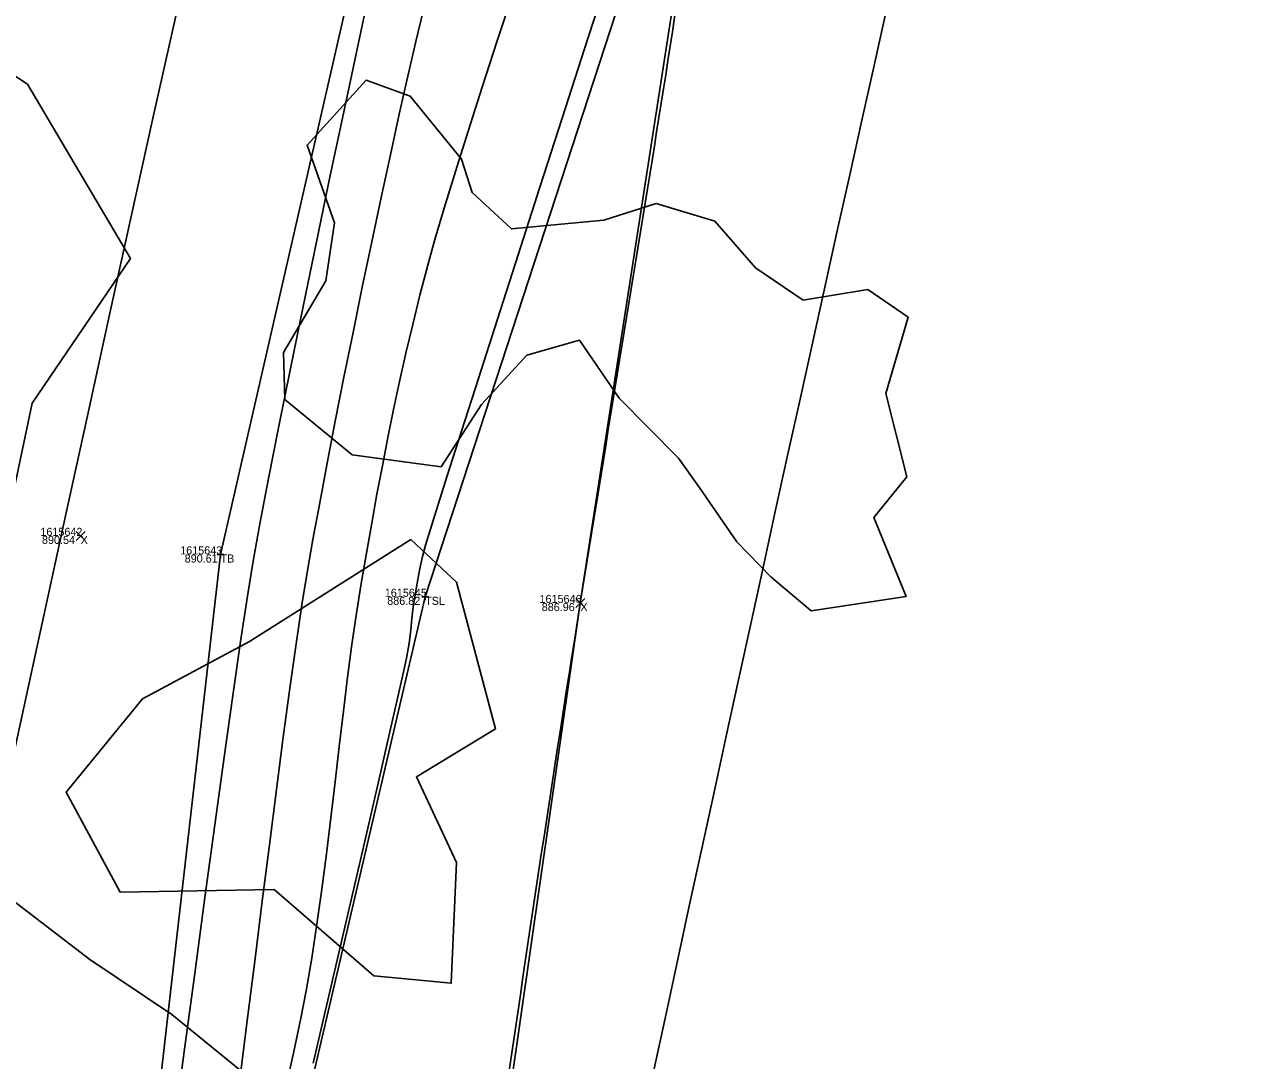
# Model space of a CAD drawing. Extents: x 1957117 to 1971063, y 701601 to 715861.
# Drawn here: x 1962867.2 to 1962920.6, y 704121 to 704165.9 of the extents above; entities that cross this region are included whole.
import ezdxf

# ---------------------------------------------------------------- set-up
doc = ezdxf.new("R2010")
doc.units = 0
for name, color, linetype in [('AP_X_Lights', 7, 'Continuous'), ('DT_X_Break_Line', 7, 'Continuous'), ('DT_X_Contour_Major', 7, 'Continuous'), ('DT_X_Contour_Minor', 7, 'Continuous'), ('DT_X_TIN_Hull', 7, 'Continuous'), ('GE_X_CL_20', 7, 'Continuous'), ('HY_X_Water_Edge', 7, 'Continuous'), ('PV_P_Drive', 7, 'Continuous'), ('PV_P_Shoulder', 7, 'Continuous'), ('RS_Raster1', 7, 'Continuous'), ('RW_X_Esmt_RR', 7, 'Continuous'), ('SC_Scratch1', 7, 'Continuous'), ('VG_X_Tree_Line_Rt', 7, 'Continuous')]:
    doc.layers.add(name, color=color, linetype=linetype)

msp = doc.modelspace()

# ---------------------------------------------------------------- linework, layer by layer
at = {"layer": 'AP_X_Lights'}
for p, q in [((1962869.397, 704143.569), (1962869.785, 704143.959)), ((1962869.397, 704143.959), (1962869.785, 704143.569)), ((1962891.047, 704140.659), (1962891.435, 704141.049)), ((1962891.047, 704141.049), (1962891.435, 704140.659))]:
    msp.add_line(p, q, dxfattribs=at)
at = {"layer": 'DT_X_Break_Line'}
for points in [[(1962943.949, 704328.022), (1962905.467, 704230.979), (1962897.382, 704180.529), (1962884.517, 704141.123), (1962873.17, 704092.531), (1962861.357, 704043.493), (1962859.494, 703994.644), (1962847.336, 703945.791), (1962836.6, 703895.416), (1962825.781, 703849.035), (1962810.838, 703749.706), (1962817.97, 703697.316), (1962817.962, 703593.874), (1962775.136, 703505.909), (1962781.746, 703450.546)], [(1962773.34, 703451.658), (1962770.93, 703504.314), (1962788.88, 703601.143), (1962786.588, 703649.417), (1962805.729, 703698.412), (1962807.65, 703752.461), (1962811.117, 703798.827), (1962819.396, 703847.658), (1962831.04, 703896.555), (1962840.848, 703945.281), (1962846.53, 703997.82), (1962856.691, 704040.715), (1962869.943, 704092.882), (1962875.651, 704142.958), (1962884.844, 704183.087), (1962898.502, 704228.866), (1962909.862, 704285.214)]]:
    msp.add_lwpolyline(points, dxfattribs=at)
at = {"layer": 'DT_X_Contour_Major'}
msp.add_lwpolyline([(1962882.214, 704167.881), (1962881.625, 704165.127), (1962881.019, 704162.276), (1962880.409, 704159.384), (1962879.807, 704156.506), (1962879.226, 704153.698), (1962878.678, 704151.016), (1962878.175, 704148.516), (1962877.731, 704146.254), (1962877.357, 704144.285), (1962877.066, 704142.665), (1962876.819, 704141.148), (1962876.523, 704139.187), (1962876.183, 704136.842), (1962875.807, 704134.173), (1962875.402, 704131.237), (1962874.975, 704128.094), (1962874.533, 704124.803), (1962874.084, 704121.422), (1962873.634, 704118.012)], dxfattribs=at)
msp.add_lwpolyline([(1962882.214, 704167.881), (1962881.625, 704165.127), (1962881.019, 704162.276), (1962880.409, 704159.384), (1962879.807, 704156.506), (1962879.226, 704153.698), (1962878.678, 704151.016), (1962878.175, 704148.516), (1962877.731, 704146.254), (1962877.357, 704144.285), (1962877.066, 704142.665), (1962876.819, 704141.148), (1962876.523, 704139.187), (1962876.183, 704136.842), (1962875.807, 704134.173), (1962875.402, 704131.237), (1962874.975, 704128.094), (1962874.533, 704124.803), (1962874.084, 704121.422), (1962873.634, 704118.012)], dxfattribs=at)
at = {"layer": 'DT_X_Contour_Minor'}
for points in [[(1962892.371, 704167.814), (1962891.424, 704164.875), (1962890.457, 704161.87), (1962889.492, 704158.869), (1962888.55, 704155.942), (1962887.656, 704153.158), (1962886.831, 704150.588), (1962886.097, 704148.3), (1962885.479, 704146.364), (1962884.997, 704144.85), (1962884.675, 704143.828), (1962884.534, 704143.367), (1962884.408, 704142.873), (1962884.316, 704142.478), (1962884.242, 704142.115), (1962884.171, 704141.716), (1962884.084, 704141.213), (1962884.003, 704140.673), (1962883.946, 704140.176), (1962883.891, 704139.674), (1962883.82, 704139.117), (1962883.712, 704138.457), (1962883.598, 704137.931), (1962883.339, 704136.783), (1962882.951, 704135.087), (1962882.451, 704132.914), (1962881.856, 704130.337), (1962881.183, 704127.43), (1962880.45, 704124.264), (1962879.673, 704120.913)], [(1962892.371, 704167.814), (1962891.424, 704164.875), (1962890.457, 704161.87), (1962889.492, 704158.869), (1962888.55, 704155.942), (1962887.656, 704153.158), (1962886.831, 704150.588), (1962886.097, 704148.3), (1962885.479, 704146.364), (1962884.997, 704144.85), (1962884.675, 704143.828), (1962884.534, 704143.367), (1962884.408, 704142.873), (1962884.316, 704142.478), (1962884.242, 704142.115), (1962884.171, 704141.716), (1962884.084, 704141.213), (1962884.003, 704140.673), (1962883.946, 704140.176), (1962883.891, 704139.674), (1962883.82, 704139.117), (1962883.712, 704138.457), (1962883.598, 704137.931), (1962883.339, 704136.783), (1962882.951, 704135.087), (1962882.451, 704132.914), (1962881.856, 704130.337), (1962881.183, 704127.43), (1962880.45, 704124.264), (1962879.673, 704120.913)], [(1962888.319, 704167.279), (1962887.644, 704165.214), (1962886.995, 704163.211), (1962886.385, 704161.31), (1962885.829, 704159.549), (1962885.342, 704157.967), (1962884.937, 704156.603), (1962884.629, 704155.495), (1962884.293, 704154.195), (1962883.98, 704152.928), (1962883.687, 704151.684), (1962883.412, 704150.458), (1962883.152, 704149.24), (1962882.903, 704148.024), (1962882.664, 704146.802), (1962882.431, 704145.565), (1962882.202, 704144.307), (1962881.974, 704143.02), (1962881.745, 704141.697), (1962881.539, 704140.419), (1962881.344, 704139.061), (1962881.157, 704137.637), (1962880.974, 704136.159), (1962880.794, 704134.641), (1962880.613, 704133.097), (1962880.429, 704131.541), (1962880.238, 704129.986), (1962880.039, 704128.445), (1962879.828, 704126.933), (1962879.602, 704125.463), (1962879.359, 704124.048), (1962879.129, 704122.866), (1962878.824, 704121.415), (1962878.455, 704119.73)], [(1962888.319, 704167.279), (1962887.644, 704165.214), (1962886.995, 704163.211), (1962886.385, 704161.31), (1962885.829, 704159.549), (1962885.342, 704157.967), (1962884.937, 704156.603), (1962884.629, 704155.495), (1962884.293, 704154.195), (1962883.98, 704152.928), (1962883.687, 704151.684), (1962883.412, 704150.458), (1962883.152, 704149.24), (1962882.903, 704148.024), (1962882.664, 704146.802), (1962882.431, 704145.565), (1962882.202, 704144.307), (1962881.974, 704143.02), (1962881.745, 704141.697), (1962881.539, 704140.419), (1962881.344, 704139.061), (1962881.157, 704137.637), (1962880.974, 704136.159), (1962880.794, 704134.641), (1962880.613, 704133.097), (1962880.429, 704131.541), (1962880.238, 704129.986), (1962880.039, 704128.445), (1962879.828, 704126.933), (1962879.602, 704125.463), (1962879.359, 704124.048), (1962879.129, 704122.866), (1962878.824, 704121.415), (1962878.455, 704119.73)], [(1962884.439, 704166.506), (1962884.119, 704165.185), (1962883.771, 704163.689), (1962883.399, 704162.044), (1962883.01, 704160.279), (1962882.609, 704158.423), (1962882.202, 704156.502), (1962881.794, 704154.545), (1962881.392, 704152.58), (1962881, 704150.635), (1962880.626, 704148.737), (1962880.273, 704146.915), (1962879.948, 704145.196), (1962879.657, 704143.609), (1962879.406, 704142.181), (1962879.177, 704140.772), (1962878.927, 704139.084), (1962878.658, 704137.159), (1962878.373, 704135.039), (1962878.076, 704132.765), (1962877.771, 704130.38), (1962877.46, 704127.926), (1962877.148, 704125.445), (1962876.838, 704122.978), (1962876.533, 704120.567)], [(1962884.439, 704166.506), (1962884.119, 704165.185), (1962883.771, 704163.689), (1962883.399, 704162.044), (1962883.01, 704160.279), (1962882.609, 704158.423), (1962882.202, 704156.502), (1962881.794, 704154.545), (1962881.392, 704152.58), (1962881, 704150.635), (1962880.626, 704148.737), (1962880.273, 704146.915), (1962879.948, 704145.196), (1962879.657, 704143.609), (1962879.406, 704142.181), (1962879.177, 704140.772), (1962878.927, 704139.084), (1962878.658, 704137.159), (1962878.373, 704135.039), (1962878.076, 704132.765), (1962877.771, 704130.38), (1962877.46, 704127.926), (1962877.148, 704125.445), (1962876.838, 704122.978), (1962876.533, 704120.567)]]:
    msp.add_lwpolyline(points, dxfattribs=at)
at = {"layer": 'DT_X_TIN_Hull'}
msp.add_lwpolyline([(1962804.686, 703399.836), (1962817.962, 703593.874), (1962817.97, 703697.316), (1962826.397, 703745.681), (1962828.582, 703804.235), (1962836.461, 703844.734), (1962850.687, 703896.004), (1962867.251, 703938.846), (1962873.848, 703992.355), (1962884.135, 704091.371), (1962891.241, 704140.854), (1962897.382, 704180.529), (1962905.467, 704230.979), (1962909.862, 704285.214)], dxfattribs=at)
at = {"layer": 'GE_X_CL_20'}
msp.add_arc((1968466.781, 702923.066), 5729.578, 166.495347, 177.813939, dxfattribs=at)
at = {"layer": 'HY_X_Water_Edge'}
msp.add_spline([(1963191.723, 701994.048), (1963062.047, 702441.167), (1962863.491, 703169.356), (1962827.53, 703438.691), (1962823.213, 703537.412), (1962817.962, 703593.874), (1962817.97, 703697.316), (1962828.582, 703804.235), (1962836.461, 703844.734), (1962850.687, 703896.004), (1962867.251, 703938.846), (1962873.848, 703992.355), (1962884.135, 704091.371), (1962891.241, 704140.854), (1962897.382, 704180.529), (1962905.467, 704230.979), (1962943.949, 704328.022), (1962948.537, 704378.842), (1962964.114, 704426.264), (1963004.885, 704570.73), (1963042.054, 704716.522), (1963062.038, 704814.417), (1963072.171, 704860.237), (1963090.023, 704956.798), (1963107.066, 705031.783), (1963133.773, 705105.742), (1963148.685, 705206.74), (1963175.48, 705301.059), (1963191.635, 705353.417), (1963210.988, 705447.286), (1963219.532, 705497.27), (1963230.124, 705549.475), (1963251.052, 705591.159), (1963275.289, 705693.429), (1963292.982, 705784.032), (1963302.841, 705839.645), (1963335.126, 705936.766), (1963359.752, 706046.75), (1963389.133, 706177.299), (1963417.827, 706273.456), (1963475.868, 706451.902), (1963533.782, 706640.53), (1963553.86, 706696.984), (1963580.184, 706715.425), (1963609.172, 706718.73), (1963617.062, 706714.691), (1963619.447, 706694.678), (1963564.282, 706533.07), (1963531.853, 706395.229), (1963434.4, 706006.96), (1963354.09, 705679.186), (1963237.513, 705206.07), (1963167.369, 704892.962), (1963059.145, 704434.176), (1962907.914, 703908.742), (1962877.458, 703703.326), (1962898.357, 703412.121), (1962942.65, 703052.267), (1963048.963, 702674.866), (1963191.468, 702189.666), (1963245.396, 702019.832)], degree=3, dxfattribs=at)
at = {"layer": 'PV_P_Drive'}
for p, q in [((1962875.505, 704142.958), (1962875.797, 704142.958)), ((1962875.651, 704143.104), (1962875.651, 704142.812)), ((1962875.651, 704142.958), (1962875.651, 704142.958)), ((1962884.517, 704141.269), (1962884.517, 704140.977)), ((1962884.371, 704141.123), (1962884.663, 704141.123)), ((1962884.517, 704141.123), (1962884.517, 704141.123))]:
    msp.add_line(p, q, dxfattribs=at)
at = {"layer": 'RW_X_Esmt_RR'}
msp.add_arc((1968466.781, 702923.066), 5699.578, 166.495347, 172.904425, dxfattribs=at)
at = {"layer": 'VG_X_Tree_Line_Rt'}
for points in [[(1962882.795, 704034.298), (1962885.248, 704041.793), (1962884.482, 704055.8), (1962885.404, 704065.908), (1962882.366, 704072.7), (1962882.543, 704081.484), (1962882.619, 704089.681), (1962882.279, 704098.622), (1962881.961, 704108.953), (1962879.902, 704115.666), (1962876.89, 704120.283), (1962873.54, 704123.024), (1962869.986, 704125.403), (1962863.467, 704130.399), (1962863.467, 704130.399), (1962867.485, 704149.521), (1962871.749, 704155.787), (1962867.283, 704163.333), (1962860.619, 704167.72)], [(1962881.357, 704147.282), (1962885.212, 704146.76), (1962886.961, 704149.461), (1962888.92, 704151.595), (1962891.2, 704152.249), (1962892.92, 704149.726), (1962895.496, 704147.124), (1962896.391, 704145.881), (1962898.029, 704143.505), (1962899.498, 704141.994), (1962901.241, 704140.515), (1962905.354, 704141.132), (1962903.955, 704144.564), (1962905.391, 704146.324), (1962904.471, 704149.935), (1962905.446, 704153.24), (1962903.7, 704154.437), (1962900.896, 704153.975), (1962898.832, 704155.374), (1962897.065, 704157.397), (1962894.532, 704158.172), (1962892.254, 704157.44), (1962888.261, 704157.077), (1962886.56, 704158.638), (1962886.1, 704160.089), (1962883.871, 704162.813), (1962881.964, 704163.519), (1962879.402, 704160.698), (1962880.586, 704157.332), (1962880.212, 704154.822), (1962878.377, 704151.716), (1962878.442, 704149.668), (1962881.357, 704147.282)], [(1962876.901, 704139.185), (1962872.266, 704136.703), (1962868.962, 704132.649), (1962871.301, 704128.328), (1962877.979, 704128.433), (1962882.296, 704124.691), (1962885.648, 704124.373), (1962885.869, 704129.611), (1962884.14, 704133.318), (1962887.571, 704135.4), (1962885.876, 704141.763), (1962883.904, 704143.6), (1962876.901, 704139.185)]]:
    msp.add_lwpolyline(points, dxfattribs=at)

# ---------------------------------------------------------------- texts
at = {"layer": 'PV_P_Shoulder'}
for s, p in [('890.54', (1962867.916, 704143.414)), ('890.61', (1962874.099, 704142.608)), ('886.82', (1962882.875, 704140.773)), ('886.96', (1962889.568, 704140.504))]:
    msp.add_text(s, height=0.35, dxfattribs=at).set_placement(p)
at = {"layer": 'RS_Raster1'}
for s, p in [('1615642', (1962867.847, 704143.764)), ('1615643', (1962873.904, 704142.958)), ('1615645', (1962882.77, 704141.123)), ('1615646', (1962889.472, 704140.854))]:
    msp.add_text(s, height=0.35, dxfattribs=at).set_placement(p)
at = {"layer": 'SC_Scratch1'}
for s, p in [('X', (1962869.591, 704143.414)), ('TB', (1962875.651, 704142.608)), ('TSL', (1962884.517, 704140.773)), ('X', (1962891.241, 704140.504))]:
    msp.add_text(s, height=0.35, dxfattribs=at).set_placement(p)

doc.saveas('drawing.dxf')
